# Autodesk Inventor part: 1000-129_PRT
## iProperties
Created: 2006-10
Part Number: 1000-129_PRT
Document SubType Name: Modeling
Designer: Andy Moles
Density: 1 g/cm^3
Mass: 5.4781 g
Surface Area: 31.9358 cm^2
Volume: 5.4781 cm^3
Author: Andy Moles
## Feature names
1. Base1
